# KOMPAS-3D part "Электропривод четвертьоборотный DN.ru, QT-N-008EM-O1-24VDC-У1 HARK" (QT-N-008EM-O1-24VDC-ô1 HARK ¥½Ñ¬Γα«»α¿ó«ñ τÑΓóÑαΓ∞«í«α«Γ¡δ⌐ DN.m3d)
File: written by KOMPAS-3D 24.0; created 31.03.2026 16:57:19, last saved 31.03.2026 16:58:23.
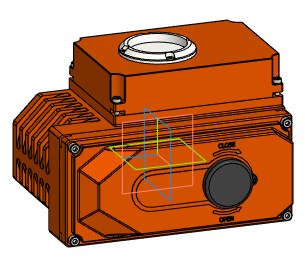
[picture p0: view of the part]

Document properties: Автор: DN.RU; Полное имя файла: D:\PROJECT CAD\DN.RU\...195\Исходники\24В\QT-N-008EM-O1-24VDC-У1 HARK Электропривод четвертьоборотный DN.ru\QT-N-008EM-O1-24VDC-У1 HARK Электропривод четвертьоборотный DN.m3d

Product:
- Body: Твердое тело1  | qty 1
    Масса: 13.49229
- Part/product: Электропривод четвертьоборотный DN.ru  | designation QT-N-008EM-O1-24VDC-У1 HARK
    Масса: 3.6
    Раздел спецификации: Прочие изделия
    Комментарий: D300-14481
    Примечание: D300-14482
    additional columns: Сталь

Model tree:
1. Твердое тело1  (labels: Твердое тело1)

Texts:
  QT-N-008EM-O1-24VDC-У1 HARK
